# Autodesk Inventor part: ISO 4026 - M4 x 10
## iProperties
Comments: To add or edit properties for Autodesk Inventor files, use iProperties.
Created: 2004-08
Part Number: ISO 4026 - M4 x 10
Vendor: Autodesk Inc.
Document SubType Name: Modeling
Designer: John Blackburn
Material: Default
Description: Hexagon Socket Set Screw
Standard: ISO 4026
Alert: To add or edit properties for Autodesk Inventor files, use iProperties.
Control State: 0
Master: False
Checked Out: False
Shininess: 64.0
Length Units: 11269
Angle Units: 11279
Time Units: 11290
Mass Units: 11283
Length Display Precision: 3
Angle Display Precision: 2
Compacted: True
EGR: 1
Density: 0.0
Volumn: 0.0
Area: 0.0
PropertySet Name: Model Information
Author: John Blackburn
Revision Number: 8
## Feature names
1. Body [Revolution]
2. Chamfer1
3. Slot [Extrusion]
4. Chamfer2
